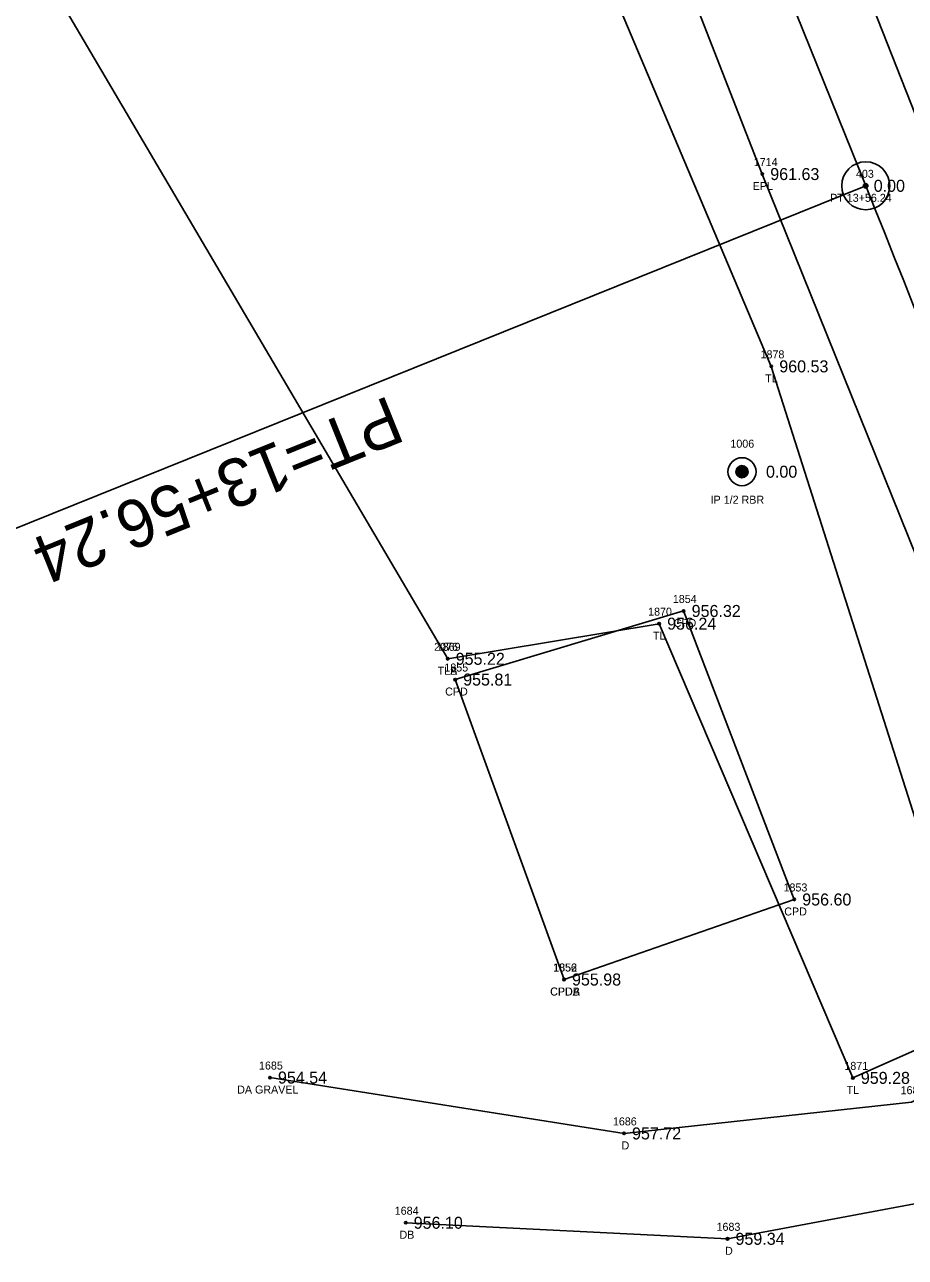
# Model space of a CAD drawing. Extents: x 1528109 to 1531398, y 1157799 to 1162548.
# Drawn here: x 1530505.4 to 1530615.5, y 1158727.4 to 1158881.4 of the extents above; entities that cross this region are included whole.
import ezdxf

# ---------------------------------------------------------------- set-up
doc = ezdxf.new("R2010")
doc.units = 0
for name, color, linetype in [('RD_EX_Conc', 7, 'Continuous'), ('RD_EX_Conc_txCode', 7, 'Continuous'), ('RD_EX_Driveway', 7, 'Continuous'), ('RD_EX_Driveway_txCode', 7, 'Continuous'), ('RD_EX_DV_Prop_txCode', 7, 'Continuous'), ('RD_EX_DV_PropPin', 7, 'Continuous'), ('RD_EX_Road', 7, 'Continuous'), ('RD_EX_Road_txCode', 7, 'Continuous'), ('RD_EX_TX_Conc_ELEV', 7, 'Continuous'), ('RD_EX_TX_Driveway_ELEV', 7, 'Continuous'), ('RD_EX_TX_DV_Prop_ELEV', 7, 'Continuous'), ('RD_EX_TX_Road_ELEV', 7, 'Continuous'), ('RD_EX_TX_VEG_ELEV', 7, 'Continuous'), ('RD_EX_VEG', 7, 'Continuous'), ('RD_EX_VEG_txCode', 7, 'Continuous'), ('RD_HC_Cl', 7, 'Continuous'), ('RD_HC_Data', 7, 'Continuous'), ('RD_HC_Survey_ELEV', 7, 'Continuous'), ('RD_HC_txCode', 7, 'Continuous'), ('RD_SMD_Locator', 7, 'Continuous')]:
    doc.layers.add(name, color=color, linetype=linetype)

msp = doc.modelspace()

# ---------------------------------------------------------------- linework, layer by layer
at = {"layer": 'RD_EX_Conc'}
msp.add_lwpolyline([(1530572.84, 1158762.14), (1530601.61, 1158772.14), (1530587.79, 1158808.19), (1530559.24, 1158799.62), (1530572.84, 1158762.14)], dxfattribs=at)
at = {"layer": 'RD_EX_Driveway'}
for points in [[(1530536.1, 1158749.89), (1530580.34, 1158742.91), (1530616.27, 1158746.81), (1530638.95, 1158757.58)], [(1530644.65, 1158739.35), (1530593.27, 1158729.74), (1530553.06, 1158731.75)]]:
    msp.add_lwpolyline(points, dxfattribs=at)
at = {"layer": 'RD_EX_DV_PropPin'}
for p, q in [((1530594.59, 1158825), (1530594.59, 1158826.17)), ((1530594.62, 1158824.98), (1530594.62, 1158826.2)), ((1530594.66, 1158824.95), (1530594.66, 1158826.22)), ((1530594.69, 1158824.93), (1530594.69, 1158826.24)), ((1530594.73, 1158824.91), (1530594.73, 1158826.26)), ((1530594.76, 1158824.89), (1530594.76, 1158826.28)), ((1530594.8, 1158824.88), (1530594.8, 1158826.29)), ((1530594.83, 1158824.87), (1530594.83, 1158826.31)), ((1530594.87, 1158824.86), (1530594.87, 1158826.32)), ((1530594.9, 1158824.85), (1530594.9, 1158826.33)), ((1530594.94, 1158824.84), (1530594.94, 1158826.34)), ((1530594.97, 1158824.83), (1530594.97, 1158826.34)), ((1530595.01, 1158824.83), (1530595.01, 1158826.34)), ((1530595.04, 1158824.83), (1530595.04, 1158826.35)), ((1530595.08, 1158824.83), (1530595.08, 1158826.35)), ((1530595.11, 1158824.83), (1530595.11, 1158826.35)), ((1530595.15, 1158824.83), (1530595.15, 1158826.34)), ((1530595.18, 1158824.83), (1530595.18, 1158826.34)), ((1530595.22, 1158824.84), (1530595.22, 1158826.34)), ((1530595.25, 1158824.85), (1530595.25, 1158826.33)), ((1530595.29, 1158824.86), (1530595.29, 1158826.32)), ((1530595.32, 1158824.87), (1530595.32, 1158826.31)), ((1530595.36, 1158824.88), (1530595.36, 1158826.29)), ((1530595.39, 1158824.89), (1530595.39, 1158826.28)), ((1530595.43, 1158824.91), (1530595.43, 1158826.26)), ((1530595.46, 1158824.93), (1530595.46, 1158826.24)), ((1530595.5, 1158824.95), (1530595.5, 1158826.22)), ((1530595.53, 1158824.98), (1530595.53, 1158826.2)), ((1530595.57, 1158825), (1530595.57, 1158826.17)), ((1530594.34, 1158825.39), (1530594.34, 1158825.78)), ((1530594.38, 1158825.29), (1530594.38, 1158825.88)), ((1530594.41, 1158825.22), (1530594.41, 1158825.96)), ((1530594.45, 1158825.16), (1530594.45, 1158826.01)), ((1530594.48, 1158825.11), (1530594.48, 1158826.06)), ((1530594.52, 1158825.07), (1530594.52, 1158826.1)), ((1530594.55, 1158825.04), (1530594.55, 1158826.14)), ((1530595.6, 1158825.04), (1530595.6, 1158826.14)), ((1530595.64, 1158825.07), (1530595.64, 1158826.1)), ((1530595.67, 1158825.11), (1530595.67, 1158826.06)), ((1530595.71, 1158825.16), (1530595.71, 1158826.01)), ((1530595.74, 1158825.22), (1530595.74, 1158825.96)), ((1530595.78, 1158825.29), (1530595.78, 1158825.88)), ((1530595.81, 1158825.39), (1530595.81, 1158825.78))]:
    msp.add_line(p, q, dxfattribs=at)
for radius in [1.75, 0.761]:
    msp.add_circle((1530595.08, 1158825.59), radius, dxfattribs=at)
at = {"layer": 'RD_EX_Road'}
for points in [[(1530704.87, 1158597.47), (1530691.01, 1158649.88), (1530681.22, 1158687.32), (1530670.59, 1158725), (1530654.42, 1158774.07), (1530635.35, 1158823.15), (1530627.8, 1158842.3), (1530617.35, 1158868.69), (1530597.91, 1158918.04), (1530578.53, 1158967.57), (1530556.7, 1159015.66), (1530524.51, 1159062.45), (1530499.94, 1159086.31), (1530481.93, 1159100.12), (1530434.53, 1159127), (1530416.95, 1159134.13), (1530380.01, 1159145.61), (1530337.52, 1159156.44)], [(1530685.41, 1158592.23), (1530678.87, 1158616.46), (1530671.67, 1158642.17), (1530661.52, 1158682.33), (1530651.17, 1158718.79), (1530644.65, 1158739.35), (1530638.95, 1158757.58), (1530635.45, 1158767.4), (1530616.88, 1158814.94), (1530597.61, 1158862.78), (1530579.09, 1158910.21), (1530559.73, 1158959.38), (1530538.76, 1159006.16), (1530508.96, 1159048.3), (1530469.44, 1159083.44), (1530424.03, 1159108.51), (1530374.97, 1159125.76), (1530332.28, 1159136.67)]]:
    msp.add_lwpolyline(points, dxfattribs=at)
at = {"layer": 'RD_EX_VEG'}
msp.add_lwpolyline([(1530558.31, 1158802.21), (1530584.73, 1158806.6), (1530608.93, 1158749.85), (1530624.81, 1158756.88), (1530598.74, 1158838.75), (1530544.19, 1158967.8), (1530499.65, 1159033.34), (1530444.6, 1159080.15), (1530373.76, 1159115.62), (1530558.31, 1158802.21)], dxfattribs=at)
at = {"layer": 'RD_HC_Cl'}
msp.add_line((1530610.54, 1158861.31), (1530562.18, 1158981.29), dxfattribs=at)
msp.add_arc((1528952, 1158192.73), 1788.23, 15.39728, 21.95502, dxfattribs=at)
at = {"layer": 'RD_HC_Data'}
msp.add_line((1530610.54, 1158861.31), (1530503.27, 1158818.06), dxfattribs=at)
for radius in [3, 0.282]:
    msp.add_circle((1530610.54, 1158861.31), radius, dxfattribs=at)
at = {"layer": 'RD_SMD_Locator'}
for centre in [(1530597.61, 1158862.78), (1530610.54, 1158861.31), (1530598.74, 1158838.75), (1530595.08, 1158825.59), (1530587.79, 1158808.19), (1530584.73, 1158806.6), (1530558.31, 1158802.21), (1530558.31, 1158802.21), (1530559.24, 1158799.62), (1530601.61, 1158772.14), (1530572.84, 1158762.14), (1530572.84, 1158762.14), (1530536.1, 1158749.89), (1530608.93, 1158749.85), (1530580.34, 1158742.91), (1530553.06, 1158731.75), (1530593.27, 1158729.74)]:
    msp.add_circle(centre, 0.15, dxfattribs=at)

# ---------------------------------------------------------------- texts
at = {"layer": 'RD_EX_Conc_txCode'}
for s, p in [('1854', (1530586.44, 1158809.19)), ('CPD', (1530586.54, 1158806.19)), ('1855', (1530557.89, 1158800.62)), ('CPD', (1530557.99, 1158797.62)), ('1853', (1530600.27, 1158773.14)), ('CPD', (1530600.36, 1158770.14)), ('1856', (1530571.47, 1158763.14)), ('1852', (1530571.5, 1158763.14)), ('CPDA', (1530571.1, 1158760.14)), ('CPDB', (1530571.12, 1158760.14))]:
    msp.add_text(s, height=1, dxfattribs=at).set_placement(p)
at = {"layer": 'RD_EX_Driveway_txCode'}
for s, p in [('1685', (1530534.73, 1158750.89)), ('DA GRAVEL', (1530532, 1158747.89)), ('1687', (1530614.9, 1158747.81)), ('1686', (1530578.95, 1158743.91)), ('D', (1530580.03, 1158740.91)), ('1684', (1530551.69, 1158732.75)), ('DB', (1530552.28, 1158729.75)), ('1683', (1530591.9, 1158730.74)), ('D', (1530592.96, 1158727.74))]:
    msp.add_text(s, height=1, dxfattribs=at).set_placement(p)
at = {"layer": 'RD_EX_DV_Prop_txCode'}
for s, p in [('1006', (1530593.63, 1158828.59)), ('IP 1/2 RBR', (1530591.16, 1158821.59))]:
    msp.add_text(s, height=1, dxfattribs=at).set_placement(p)
at = {"layer": 'RD_EX_Road_txCode'}
for s, p in [('1714', (1530596.55, 1158863.78)), ('EPL', (1530596.41, 1158860.78))]:
    msp.add_text(s, height=1, dxfattribs=at).set_placement(p)
at = {"layer": 'RD_EX_TX_Conc_ELEV'}
for s, p in [('956.32', (1530588.79, 1158807.44)), ('955.81', (1530560.24, 1158798.87)), ('956.60', (1530602.61, 1158771.39)), ('955.98', (1530573.84, 1158761.39)), ('955.98', (1530573.84, 1158761.39))]:
    msp.add_text(s, height=1.5, dxfattribs=at).set_placement(p)
at = {"layer": 'RD_EX_TX_Driveway_ELEV'}
for s, p in [('954.54', (1530537.1, 1158749.14)), ('957.72', (1530581.34, 1158742.16)), ('956.10', (1530554.06, 1158731)), ('959.34', (1530594.27, 1158728.99))]:
    msp.add_text(s, height=1.5, dxfattribs=at).set_placement(p)
at = {"layer": 'RD_EX_TX_DV_Prop_ELEV'}
msp.add_text('0.00', height=1.5, dxfattribs=at).set_placement((1530598.08, 1158824.84))
at = {"layer": 'RD_EX_TX_Road_ELEV'}
msp.add_text('961.63', height=1.5, dxfattribs=at).set_placement((1530598.61, 1158862.03))
at = {"layer": 'RD_EX_TX_VEG_ELEV'}
for s, p in [('960.53', (1530599.74, 1158838)), ('956.24', (1530585.73, 1158805.85)), ('955.22', (1530559.31, 1158801.46)), ('955.22', (1530559.31, 1158801.46)), ('959.28', (1530609.93, 1158749.1))]:
    msp.add_text(s, height=1.5, dxfattribs=at).set_placement(p)
at = {"layer": 'RD_EX_VEG_txCode'}
for s, p in [('1878', (1530597.4, 1158839.75)), ('TL', (1530597.97, 1158836.75)), ('1870', (1530583.35, 1158807.6)), ('TL', (1530583.96, 1158804.6)), ('2076', (1530556.61, 1158803.21)), ('1869', (1530556.94, 1158803.21)), ('TLA', (1530557.05, 1158800.21)), ('TLB', (1530557.06, 1158800.21)), ('1871', (1530607.87, 1158750.85)), ('TL', (1530608.16, 1158747.85))]:
    msp.add_text(s, height=1, dxfattribs=at).set_placement(p)
at = {"layer": 'RD_HC_Data'}
msp.add_text('PT=13+56.24', height=6, rotation=201.955, dxfattribs=at).set_placement((1530551, 1158835.15))
at = {"layer": 'RD_HC_Survey_ELEV'}
msp.add_text('0.00', height=1.5, dxfattribs=at).set_placement((1530611.54, 1158860.56))
at = {"layer": 'RD_HC_txCode'}
for s, p in [('403', (1530609.32, 1158862.31)), ('PT 13+56.24', (1530606.09, 1158859.31))]:
    msp.add_text(s, height=1, dxfattribs=at).set_placement(p)

doc.saveas('drawing.dxf')
